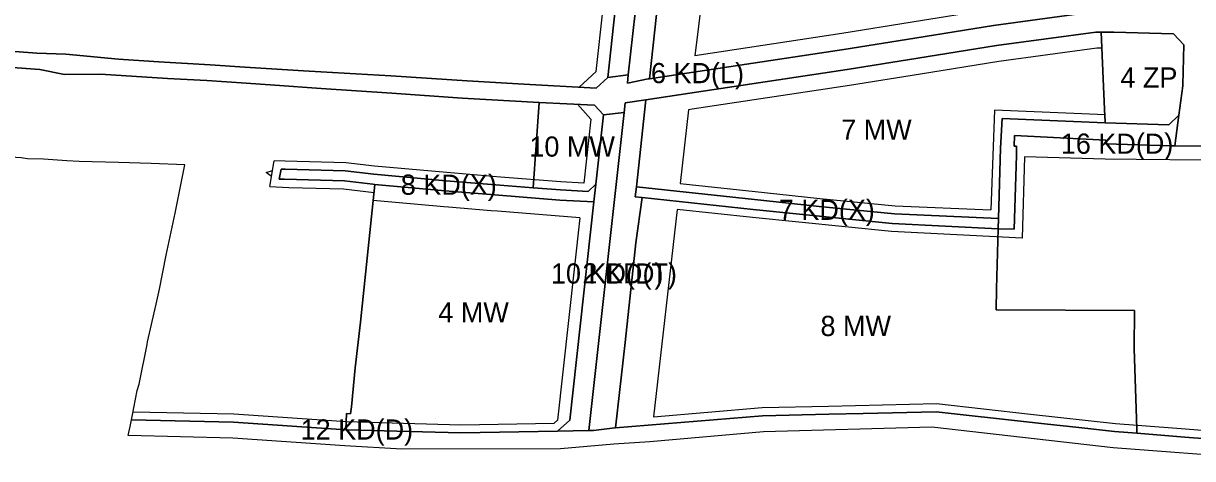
# Model space of a CAD drawing. Extents: x 7424258 to 7426021, y 5551671 to 5553193.
# Drawn here: x 7425011 to 7425590, y 5551675 to 5551891 of the extents above; entities that cross this region are included whole.
import ezdxf

# ---------------------------------------------------------------- set-up
doc = ezdxf.new("R2010")
doc.units = 0
for name, color, linetype in [('linie_rozgraniczajace', 7, 'Continuous'), ('linie_zabudowy_nieprzekraczalne', 7, 'Continuous'), ('oznaczenia_przeznaczen', 7, 'Continuous')]:
    doc.layers.add(name, color=color, linetype=linetype)

msp = doc.modelspace()

# ---------------------------------------------------------------- linework, layer by layer
at = {"layer": 'linie_rozgraniczajace'}
for p, q in [((7425038.45, 5551822.34), (7425032.31, 5551822.76)), ((7425064.38, 5551694.45), (7425064.75, 5551696.15))]:
    msp.add_line(p, q, dxfattribs=at)
for points in [[(7425310.41, 5551865.34), (7425313.81, 5551896), (7425318.39, 5551921.94), (7425325.72, 5551947.69), (7425337.66, 5551988.37), (7425341.53, 5552001.56), (7425345.87, 5552016.33), (7425353.33, 5552044.09), (7425356.47, 5552056.06), (7425363.7, 5552083.52), (7425374.33, 5552124.01), (7425377.61, 5552134.39), (7425374.35, 5552154.75), (7425379.23, 5552173.31), (7425381.04, 5552180.19), (7425382.76, 5552186.71), (7425383.93, 5552191.17), (7425385.96, 5552198.95), (7425389.47, 5552212.23), (7425392.27, 5552222.89), (7425395.93, 5552236.83), (7425398.85, 5552247.95), (7425402.13, 5552260.45), (7425404.45, 5552269.24)], [(7425421.85, 5552264.67), (7425419.54, 5552255.88), (7425416.26, 5552243.37), (7425413.33, 5552232.27), (7425409.68, 5552218.34), (7425406.88, 5552207.65), (7425403.37, 5552194.36), (7425401.34, 5552186.6), (7425400.16, 5552182.14), (7425398.44, 5552175.61), (7425396.64, 5552168.73), (7425382.23, 5552114.68), (7425376.58, 5552093.23), (7425363.97, 5552045.24), (7425348.26, 5551989.98), (7425339.27, 5551956.93), (7425336.58, 5551947.06), (7425328.59, 5551919.07), (7425324.39, 5551895.19), (7425320.85, 5551863.31), (7425320.24, 5551863.23), (7425309.95, 5551861.15), (7425310.41, 5551865.34)], [(7425303.91, 5551897.42), (7425300.21, 5551864), (7425294.45, 5551858.76), (7425258.72, 5551860.62), (7425230.65, 5551862.28), (7425192.84, 5551864.86), (7425158.15, 5551866.85), (7425149.54, 5551867.23), (7425120.45, 5551869.02), (7425103.34, 5551870.26), (7425077.99, 5551871.75), (7425057.93, 5551873.12), (7425031.87, 5551875.47), (7425017.54, 5551875.99), (7425006.57, 5551876.8)], [(7425006.57, 5551876.8), (7425017.54, 5551875.99), (7425031.87, 5551875.47), (7425057.93, 5551873.12), (7425077.99, 5551871.75), (7425103.34, 5551870.26), (7425120.45, 5551869.02), (7425149.54, 5551867.23), (7425158.15, 5551866.85), (7425192.84, 5551864.86), (7425230.65, 5551862.28), (7425258.72, 5551860.62), (7425294.45, 5551858.76), (7425300.21, 5551864), (7425310.41, 5551865.34), (7425309.95, 5551861.15), (7425320.24, 5551863.23), (7425320.85, 5551863.31), (7425339.34, 5551866.07), (7425417.17, 5551877.82), (7425452.25, 5551883.42), (7425491.27, 5551889.67), (7425531.19, 5551895.08)], [(7425313.81, 5551896), (7425310.41, 5551865.34), (7425300.21, 5551864), (7425303.91, 5551897.42)], [(7425595.25, 5551830.04), (7425581.02, 5551830.07), (7425583.09, 5551845.33), (7425585.05, 5551859.85), (7425585.06, 5551860.35), (7425585.5, 5551880.14), (7425580.42, 5551885.57), (7425550.83, 5551886.36), (7425544.52, 5551886.41), (7425541.87, 5551886.42), (7425492.74, 5551879.77), (7425453.83, 5551873.54), (7425418.75, 5551867.95), (7425340.83, 5551856.19), (7425319.12, 5551852.95), (7425308.87, 5551851.43), (7425308.34, 5551846.63), (7425298.15, 5551845.44)], [(7425298.15, 5551845.44), (7425293.7, 5551850.27), (7425266.18, 5551851.63), (7425228.16, 5551853.74), (7425193.24, 5551856.18), (7425158.31, 5551858.58), (7425135.35, 5551860.21), (7425121.08, 5551861.23), (7425101.62, 5551862.4), (7425082.13, 5551863.53), (7425048.96, 5551865.65), (7425031.24, 5551865.48), (7425019.04, 5551867.93), (7424998.6, 5551869.48)], [(7424998.6, 5551869.48), (7425019.04, 5551867.93), (7425031.24, 5551865.48), (7425048.96, 5551865.65), (7425082.13, 5551863.53), (7425101.62, 5551862.4), (7425121.08, 5551861.23), (7425135.35, 5551860.21), (7425158.31, 5551858.58), (7425193.24, 5551856.18), (7425228.16, 5551853.74), (7425266.18, 5551851.63), (7425263.26, 5551809.38), (7425246.72, 5551810.69), (7425220.21, 5551812.88), (7425184.36, 5551816.11), (7425170.15, 5551817.76)], [(7425620.82, 5551683.29), (7425586.01, 5551685.98), (7425562.17, 5551687.82), (7425562.18, 5551690.09), (7425560.91, 5551729.89), (7425561.12, 5551748.57), (7425492.59, 5551748.94), (7425492.81, 5551759.4), (7425493.56, 5551789.1), (7425501.54, 5551788.85), (7425502.63, 5551825.35), (7425502.71, 5551829.9), (7425501.54, 5551829.95), (7425501.72, 5551835.29), (7425546.84, 5551833.01), (7425546.9, 5551831.11), (7425578.93, 5551830.07), (7425581.02, 5551830.07), (7425595.25, 5551830.04)], [(7425032.31, 5551822.76), (7425020.77, 5551823.55), (7425012.91, 5551823.76), (7425009.66, 5551824.12), (7424985.59, 5551825.62), (7424983.07, 5551811.29), (7424980.32, 5551800.43), (7424980.26, 5551799.25), (7424978.71, 5551794.76), (7424958.8, 5551799.48), (7424944.69, 5551802.76), (7424939.44, 5551782.44), (7424930.64, 5551747.51), (7424930.26, 5551746.88)], [(7425064.75, 5551696.15), (7425067.1, 5551709.09), (7425068.11, 5551712.09), (7425072.18, 5551731.79), (7425072.29, 5551733.14), (7425076.64, 5551751.69), (7425078.17, 5551759.13), (7425081.59, 5551775.93), (7425085.94, 5551796.73), (7425090.72, 5551820.74), (7425074.13, 5551821.36), (7425058.01, 5551821.89), (7425038.45, 5551822.34)], [(7425170.15, 5551817.76), (7425140.4, 5551818.55), (7425138.43, 5551818.64), (7425137.55, 5551813.68), (7425140.22, 5551813.56), (7425169.79, 5551812.77), (7425183.85, 5551811.14), (7425184.84, 5551811.05), (7425177.72, 5551742.83), (7425175.14, 5551720.27), (7425173.29, 5551700.95), (7425172.83, 5551697.44), (7425170.85, 5551697.6), (7425170.46, 5551689.61), (7425114.84, 5551693.42), (7425064.38, 5551694.45)], [(7425064.38, 5551694.45), (7425114.84, 5551693.42), (7425170.46, 5551689.61), (7425227.43, 5551688.02), (7425275.26, 5551688.9), (7425290.91, 5551689.2), (7425293.12, 5551689.24), (7425302.38, 5551690.34), (7425304.11, 5551690.48), (7425376.93, 5551696.55), (7425409.67, 5551697.3), (7425426.73, 5551697.7), (7425462.78, 5551698.5), (7425509.1, 5551693.35), (7425516.5, 5551692.52), (7425533.43, 5551690.64), (7425551.21, 5551688.67), (7425562.17, 5551687.82), (7425586.01, 5551685.98), (7425620.82, 5551683.29)], [(7425062.7, 5551686.68), (7425063.68, 5551691.21), (7425064.38, 5551694.45)], [(7425620.33, 5551675.3), (7425550.46, 5551680.7), (7425460.78, 5551690.8), (7425377.35, 5551688.56), (7425321.07, 5551683.65), (7425303.18, 5551682.38), (7425276.87, 5551680.17), (7425198.29, 5551679.93), (7425170.07, 5551681.62), (7425114.48, 5551685.43), (7425062.7, 5551686.68)]]:
    msp.add_lwpolyline(points, dxfattribs=at)
for points in [[(7425320.85, 5551863.31), (7425324.39, 5551895.19), (7425328.59, 5551919.07), (7425336.58, 5551947.06), (7425347.58, 5551946.45), (7425379, 5551943.78), (7425452.35, 5551939.05), (7425535.65, 5551934.86), (7425531.19, 5551895.08), (7425491.27, 5551889.67), (7425452.25, 5551883.42), (7425417.17, 5551877.82), (7425339.34, 5551866.07)], [(7425314.39, 5551809.88), (7425319.12, 5551852.95), (7425340.83, 5551856.19), (7425418.75, 5551867.95), (7425453.83, 5551873.54), (7425492.74, 5551879.77), (7425541.87, 5551886.42), (7425544.52, 5551886.41), (7425545.64, 5551859.44), (7425546.33, 5551844.66), (7425546.55, 5551842.53), (7425546.51, 5551841.56), (7425495.59, 5551843.59), (7425494.73, 5551828.9), (7425493.7, 5551794.18), (7425442.21, 5551796.44), (7425404.86, 5551800.04), (7425377.46, 5551803.01)], [(7425544.52, 5551886.41), (7425550.83, 5551886.36), (7425580.42, 5551885.57), (7425585.5, 5551880.14), (7425585.06, 5551860.35), (7425585.05, 5551859.85), (7425583.09, 5551845.33), (7425578.04, 5551840.47), (7425578.04, 5551840.47), (7425546.51, 5551841.56), (7425546.55, 5551842.53), (7425546.33, 5551844.66), (7425545.64, 5551859.44)], [(7425263.26, 5551809.38), (7425266.18, 5551851.63), (7425293.7, 5551850.27), (7425298.15, 5551845.44), (7425294.36, 5551811.23), (7425290.6, 5551807.58), (7425276.75, 5551808.3)], [(7425290.91, 5551689.2), (7425308.34, 5551846.63), (7425308.87, 5551851.43), (7425319.12, 5551852.95), (7425314.39, 5551809.88), (7425313.79, 5551804.89), (7425317.28, 5551804.52), (7425314.16, 5551782.19), (7425308.89, 5551732.73), (7425304.11, 5551690.48), (7425302.38, 5551690.34), (7425293.12, 5551689.24)], [(7425275.26, 5551688.9), (7425281.42, 5551694.38), (7425293.39, 5551802.43), (7425294.36, 5551811.23), (7425298.15, 5551845.44), (7425308.34, 5551846.63), (7425290.91, 5551689.2)], [(7425493.56, 5551789.1), (7425493.7, 5551794.18), (7425494.73, 5551828.9), (7425495.59, 5551843.59), (7425546.51, 5551841.56), (7425578.04, 5551840.47), (7425578.04, 5551840.47), (7425583.09, 5551845.33), (7425581.02, 5551830.07), (7425578.93, 5551830.07), (7425546.9, 5551831.11), (7425546.84, 5551833.01), (7425501.72, 5551835.29), (7425501.54, 5551829.95), (7425502.71, 5551829.9), (7425502.63, 5551825.35), (7425501.54, 5551788.85)], [(7425137.55, 5551813.68), (7425138.43, 5551818.64), (7425140.4, 5551818.55), (7425170.15, 5551817.76), (7425184.36, 5551816.11), (7425220.21, 5551812.88), (7425246.72, 5551810.69), (7425263.26, 5551809.38), (7425276.75, 5551808.3), (7425290.6, 5551807.58), (7425294.36, 5551811.23), (7425293.39, 5551802.43), (7425276.42, 5551803.32), (7425246.31, 5551805.71), (7425229.86, 5551807.07), (7425219.78, 5551807.9), (7425184.84, 5551811.05), (7425183.85, 5551811.14), (7425169.79, 5551812.77), (7425140.22, 5551813.56)], [(7425170.46, 5551689.61), (7425170.85, 5551697.6), (7425172.83, 5551697.44), (7425173.29, 5551700.95), (7425175.14, 5551720.27), (7425177.72, 5551742.83), (7425184.84, 5551811.05), (7425219.78, 5551807.9), (7425229.86, 5551807.07), (7425246.31, 5551805.71), (7425276.42, 5551803.32), (7425293.39, 5551802.43), (7425281.42, 5551694.38), (7425275.26, 5551688.9), (7425227.43, 5551688.02)], [(7425314.39, 5551809.88), (7425377.46, 5551803.01), (7425404.86, 5551800.04), (7425442.21, 5551796.44), (7425493.7, 5551794.18), (7425493.56, 5551789.1), (7425441.11, 5551791.69), (7425372.23, 5551798.68), (7425317.28, 5551804.52), (7425313.79, 5551804.89)], [(7425304.11, 5551690.48), (7425308.89, 5551732.73), (7425314.16, 5551782.19), (7425317.28, 5551804.52), (7425372.23, 5551798.68), (7425441.11, 5551791.69), (7425493.56, 5551789.1), (7425492.81, 5551759.4), (7425492.59, 5551748.94), (7425561.12, 5551748.57), (7425560.91, 5551729.89), (7425562.18, 5551690.09), (7425562.17, 5551687.82), (7425551.21, 5551688.67), (7425533.43, 5551690.64), (7425516.5, 5551692.52), (7425509.1, 5551693.35), (7425462.78, 5551698.5), (7425426.73, 5551697.7), (7425409.67, 5551697.3), (7425376.93, 5551696.55)]]:
    msp.add_lwpolyline(points, close=True, dxfattribs=at)
at = {"layer": 'linie_zabudowy_nieprzekraczalne'}
for points in [[(7425286.01, 5551859.2), (7425294.49, 5551866.91), (7425294.49, 5551866.91), (7425297.96, 5551898.28), (7425302.78, 5551925.53), (7425308.23, 5551944.67)], [(7425356.74, 5551941.66), (7425353.44, 5551929.94), (7425348.99, 5551914.07), (7425346.91, 5551904.18), (7425343.38, 5551874.77)], [(7425528.02, 5551902.71), (7425490.1, 5551897.58), (7425450.99, 5551891.32), (7425416.06, 5551885.74), (7425343.38, 5551874.77)], [(7425544.8, 5551878.41), (7425542.39, 5551878.42), (7425493.9, 5551871.86), (7425455.09, 5551865.65), (7425419.94, 5551860.03), (7425342.01, 5551848.27), (7425340.25, 5551848.01)], [(7425285.16, 5551850.69), (7425291.88, 5551843.38), (7425288.38, 5551811.71)], [(7425340.25, 5551848.01), (7425336.08, 5551811.54)], [(7425546.67, 5551845.55), (7425491.75, 5551847.79), (7425489.85, 5551798.38)], [(7425132.81, 5551809.93), (7425135.1, 5551822.79)], [(7425288.38, 5551811.71), (7425277.01, 5551812.3), (7425247.04, 5551814.67), (7425220.55, 5551816.87), (7425184.77, 5551820.09), (7425170.44, 5551821.75), (7425140.54, 5551822.55), (7425135.1, 5551822.79)], [(7425506.61, 5551824.63), (7425505.41, 5551784.48), (7425440.81, 5551787.7), (7425371.82, 5551794.69), (7425334.61, 5551798.66)], [(7425728.57, 5551819.08), (7425702.18, 5551819.88), (7425595.14, 5551823.05), (7425561.91, 5551823.4), (7425546.48, 5551823.52), (7425506.61, 5551824.63)], [(7425133.67, 5551814.98), (7425131.1, 5551816.99), (7425134.24, 5551817.96)], [(7425132.81, 5551809.93), (7425142.3, 5551809.52), (7425169.44, 5551808.8), (7425184.52, 5551807.06)], [(7425336.08, 5551811.54), (7425377.89, 5551806.99), (7425405.26, 5551804.01), (7425442.48, 5551800.44), (7425489.85, 5551798.38)], [(7425286.47, 5551794.5), (7425245.67, 5551797.73), (7425242.46, 5551798), (7425221.39, 5551799.74), (7425219.09, 5551799.93), (7425184.06, 5551803.09)], [(7425334.61, 5551798.66), (7425322.9, 5551696.06)], [(7425286.47, 5551794.5), (7425275.38, 5551694.37), (7425273.7, 5551692.88)], [(7425065.17, 5551698.44), (7425115.02, 5551697.42), (7425170.65, 5551693.61), (7425227.45, 5551692.03), (7425273.7, 5551692.88)], [(7425322.9, 5551696.06), (7425376.71, 5551700.55), (7425409.58, 5551701.29), (7425462.96, 5551702.5), (7425509.54, 5551697.33), (7425551.59, 5551692.65), (7425562.48, 5551691.81), (7425586.32, 5551689.97), (7425621.06, 5551687.28), (7425699.15, 5551683.89)], [(7425215.16, 5551695.37), (7425215.16, 5551695.35)], [(7425218.99, 5551688.26), (7425218.99, 5551688.24)], [(7425231.48, 5551687.93), (7425231.48, 5551687.9)]]:
    msp.add_lwpolyline(points, dxfattribs=at)

# ---------------------------------------------------------------- texts
at = {"layer": 'oznaczenia_przeznaczen'}
for s, p in [('6 KD(L)', (7425321.63, 5551861.15)), ('4 ZP', (7425554.1, 5551858.95)), ('7 MW', (7425415.82, 5551833.16)), ('10 MW', (7425261.4, 5551824.78)), ('16 KD(D)', (7425524.57, 5551826.21)), ('8 KD(X)', (7425197.72, 5551805.9)), ('7 KD(X)', (7425384.93, 5551793.48)), ('10 KD(D)', (7425272.08, 5551761.94)), ('2 KD(T)', (7425287.68, 5551762)), ('4 MW', (7425216.31, 5551742.69)), ('8 MW', (7425405.57, 5551735.99)), ('12 KD(D)', (7425148.12, 5551684.71))]:
    msp.add_text(s, height=10, dxfattribs=at).set_placement(p)

doc.saveas('drawing.dxf')
